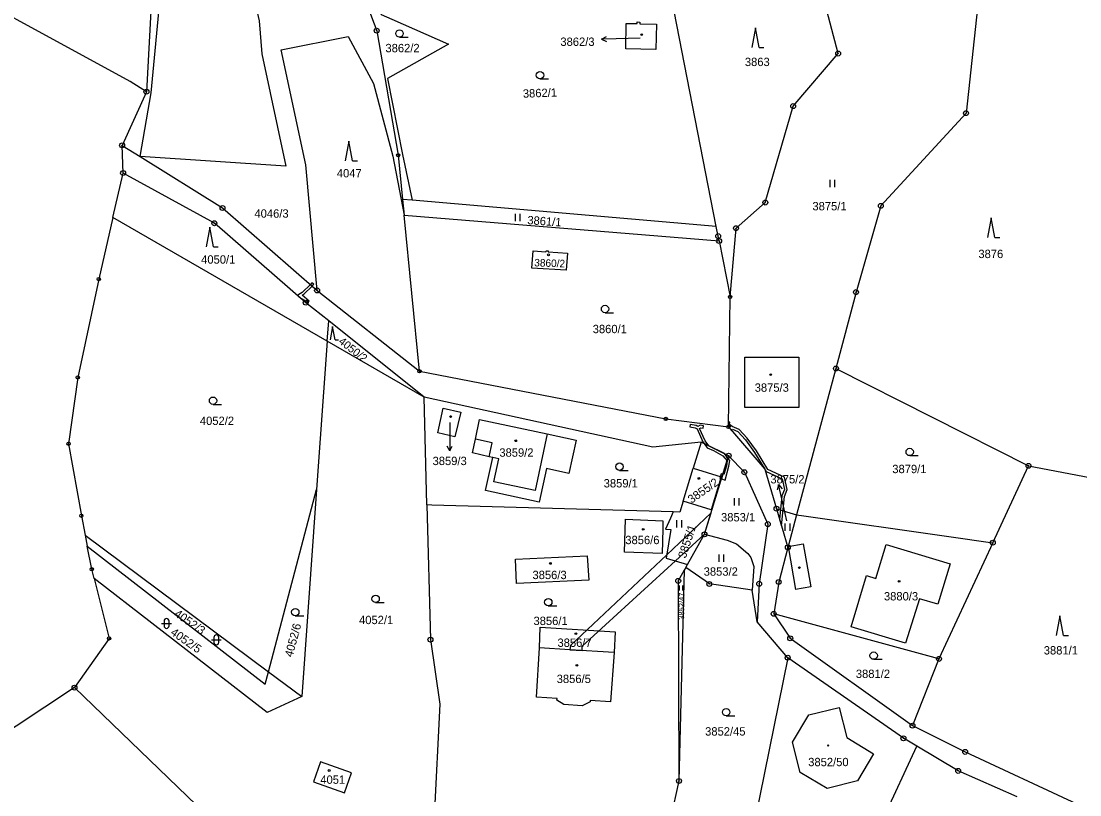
# Model space of a CAD drawing. Extents: x -644096 to -634268, y -1141430 to -1133463.
# Drawn here: x -640343 to -640127.6, y -1137528.7 to -1137371.3 of the extents above; entities that cross this region are included whole.
import ezdxf

# ---------------------------------------------------------------- set-up
doc = ezdxf.new("R2010")
doc.units = 0
for name, color, linetype in [('_CIVIL_CONSTRUCTION', 7, 'Continuous'), ('B_Hranice _3D', 7, 'Continuous'), ('M_Svah_Nasyp', 7, 'Continuous'), ('M_Svah_Zarez', 7, 'Continuous'), ('svrsek_osa_sjezdy', 7, 'Continuous'), ('svrsek_osa_VRT', 7, 'Continuous'), ('svrsek_popisy_VRT', 7, 'Continuous'), ('terminal_VRT', 7, 'Continuous')]:
    doc.layers.add(name, color=color, linetype=linetype)

msp = doc.modelspace()

# ---------------------------------------------------------------- linework, layer by layer
at = {"layer": '_CIVIL_CONSTRUCTION'}
for centre, radius in [((-640270.63, -1137373.26), 0.5), ((-640270.63, -1137373.26), 0.0303), ((-640176.73, -1137377.92), 0.5), ((-640176.73, -1137377.92), 0.0303), ((-640317.48, -1137385.68), 0.5), ((-640317.48, -1137385.68), 0.0303), ((-640185.88, -1137388.6), 0.5), ((-640185.88, -1137388.6), 0.0303), ((-640150.71, -1137390.05), 0.5), ((-640150.71, -1137390.05), 0.0303), ((-640322.44, -1137396.59), 0.5), ((-640322.44, -1137396.59), 0.0303), ((-640266.26, -1137398.59), 0.335), ((-640266.26, -1137398.59), 0.0203), ((-640322.23, -1137402.23), 0.5), ((-640322.23, -1137402.23), 0.0303), ((-640302, -1137409.33), 0.5), ((-640302, -1137409.33), 0.0303), ((-640191.55, -1137408.23), 0.5), ((-640191.55, -1137408.23), 0.0303), ((-640168.05, -1137408.9), 0.5), ((-640168.05, -1137408.9), 0.0303), ((-640303.66, -1137412.44), 0.5), ((-640303.66, -1137412.44), 0.0303), ((-640197.51, -1137413.46), 0.5), ((-640197.51, -1137413.46), 0.0303), ((-640201.15, -1137415.06), 0.5), ((-640200.95, -1137416.05), 0.5), ((-640201.15, -1137415.06), 0.0303), ((-640200.95, -1137416.05), 0.0303), ((-640327.18, -1137423.81), 0.335), ((-640327.18, -1137423.81), 0.0203), ((-640282.76, -1137426.11), 0.5), ((-640282.76, -1137426.11), 0.0303), ((-640173.09, -1137426.45), 0.5), ((-640173.09, -1137426.45), 0.0303), ((-640285.07, -1137428.61), 0.5), ((-640285.07, -1137428.61), 0.0303), ((-640198.71, -1137427.44), 0.335), ((-640198.71, -1137427.44), 0.0203), ((-640177.18, -1137442), 0.5), ((-640331.45, -1137443.82), 0.335), ((-640331.45, -1137443.82), 0.0203), ((-640261.93, -1137442.55), 0.335), ((-640261.93, -1137442.55), 0.0203), ((-640177.18, -1137442), 0.0303), ((-640211.81, -1137452.26), 0.335), ((-640211.81, -1137452.26), 0.0203), ((-640199.05, -1137453.89), 0.335), ((-640199.05, -1137453.89), 0.0203), ((-640333.34, -1137457.32), 0.335), ((-640333.34, -1137457.32), 0.0203), ((-640199.01, -1137459.74), 0.5), ((-640199.01, -1137459.74), 0.0303), ((-640195.81, -1137463.11), 0.5), ((-640195.81, -1137463.11), 0.0303), ((-640137.99, -1137461.8), 0.5), ((-640137.99, -1137461.8), 0.0303), ((-640330.73, -1137471.97), 0.335), ((-640330.73, -1137471.97), 0.0203), ((-640189.27, -1137470.53), 0.5), ((-640189.27, -1137470.53), 0.0303), ((-640191.03, -1137473.66), 0.5), ((-640191.03, -1137473.66), 0.0303), ((-640203.93, -1137475.74), 0.5), ((-640203.93, -1137475.74), 0.0303), ((-640186.97, -1137478.39), 0.5), ((-640186.97, -1137478.39), 0.0303), ((-640145.25, -1137477.45), 0.5), ((-640145.25, -1137477.45), 0.0303), ((-640328.6, -1137482.85), 0.335), ((-640328.6, -1137482.85), 0.0203), ((-640209.27, -1137485.22), 0.5), ((-640209.27, -1137485.22), 0.0303), ((-640202.94, -1137485.84), 0.5), ((-640202.94, -1137485.84), 0.0303), ((-640192.8, -1137485.8), 0.5), ((-640192.8, -1137485.8), 0.0303), ((-640188.83, -1137485.44), 0.5), ((-640188.83, -1137485.44), 0.0303), ((-640189.84, -1137491.91), 0.5), ((-640189.84, -1137491.91), 0.0303), ((-640325.09, -1137496.93), 0.335), ((-640325.09, -1137496.93), 0.0203), ((-640259.69, -1137497.17), 0.5), ((-640259.69, -1137497.17), 0.0303), ((-640186.48, -1137496.9), 0.5), ((-640186.48, -1137496.9), 0.0303), ((-640186.99, -1137500.85), 0.5), ((-640186.99, -1137500.85), 0.0303), ((-640156.21, -1137501.09), 0.5), ((-640156.21, -1137501.09), 0.0303), ((-640332.13, -1137506.94), 0.5), ((-640332.13, -1137506.94), 0.0303), ((-640161.6, -1137514.66), 0.5), ((-640161.6, -1137514.66), 0.0303), ((-640163.44, -1137517.24), 0.5), ((-640163.44, -1137517.24), 0.0303), ((-640150.88, -1137520.01), 0.5), ((-640150.88, -1137520.01), 0.0303), ((-640152.31, -1137523.88), 0.5), ((-640209.12, -1137525.92), 0.5), ((-640152.31, -1137523.88), 0.0303), ((-640209.12, -1137525.92), 0.0303)]:
    msp.add_circle(centre, radius, dxfattribs=at)
at = {"layer": 'B_Hranice _3D'}
for points in [[(-640284.13, -1137424.92), (-640283.75, -1137425.25), (-640283.42, -1137424.86), (-640283.8, -1137424.54)], [(-640284.13, -1137424.92), (-640285.77, -1137426.5), (-640286.46, -1137426.91), (-640286.76, -1137427.14), (-640286.38, -1137427.47), (-640285.33, -1137428.12), (-640284.73, -1137428.66), (-640284.39, -1137428.28), (-640285.78, -1137427.09), (-640285.47, -1137426.9), (-640283.75, -1137425.25)], [(-640206.81, -1137453.39), (-640206.9, -1137453.88), (-640205.79, -1137454.1), (-640205.43, -1137454.27), (-640204.24, -1137456.94), (-640204.02, -1137457.26), (-640203.07, -1137457.73), (-640203.8, -1137456.7), (-640204.92, -1137454.18), (-640204.72, -1137454.07), (-640204.2, -1137454.14), (-640204.13, -1137453.65), (-640204.82, -1137453.55), (-640205.25, -1137453.8), (-640205.63, -1137453.62)], [(-640198.74, -1137452.93), (-640199.04, -1137452.92), (-640199.05, -1137453.89), (-640198.74, -1137454.24), (-640198.37, -1137454.67), (-640198.25, -1137454.36), (-640197.16, -1137454.85), (-640195.59, -1137456.5), (-640193.78, -1137459.06), (-640191.63, -1137462.47), (-640191.41, -1137462.97), (-640188.1, -1137464.46), (-640187.64, -1137466.6), (-640188.16, -1137467.94), (-640188.63, -1137472.73), (-640188.25, -1137474.03), (-640187.66, -1137468.06), (-640187.12, -1137466.64), (-640187.66, -1137464.1), (-640191.07, -1137462.57), (-640193.36, -1137458.78), (-640195.21, -1137456.18), (-640196.86, -1137454.43), (-640198.28, -1137453.79), (-640198.87, -1137453.36)], [(-640204.02, -1137457.26), (-640203.4, -1137458.15), (-640202.06, -1137458.71), (-640200.21, -1137459.75), (-640199.34, -1137460.81), (-640199.16, -1137460.22), (-640199.86, -1137459.32), (-640203.07, -1137457.73)], [(-640199.16, -1137460.22), (-640199.34, -1137460.81), (-640199.47, -1137461.78), (-640199.97, -1137463.58), (-640200.17, -1137463.51), (-640200.46, -1137464.47), (-640199.75, -1137464.69), (-640198.99, -1137461.9), (-640198.76, -1137460.72)], [(-640200.53, -1137463.4), (-640200.83, -1137464.35), (-640200.46, -1137464.47), (-640200.17, -1137463.51)], [(-640202.59, -1137471.38), (-640211.59, -1137479.88), (-640231.18, -1137498.38), (-640231.31, -1137499.24), (-640228.83, -1137499.4), (-640228.79, -1137498.5), (-640209.81, -1137481.12), (-640203.93, -1137475.74)]]:
    msp.add_lwpolyline(points, close=True, dxfattribs=at)
at = {"layer": 'M_Svah_Nasyp'}
for p, q in [((-640247.11, -1137457.11), (-640250.55, -1137456.39)), ((-640235.93, -1137455.29), (-640238.39, -1137466.84)), ((-640247.74, -1137459.95), (-640247.11, -1137457.11)), ((-640245.76, -1137460.35), (-640247.02, -1137460.08)), ((-640246.79, -1137465.05), (-640245.76, -1137460.35)), ((-640238.39, -1137466.84), (-640246.79, -1137465.05)), ((-640186.93, -1137478.24), (-640183.82, -1137477.68)), ((-640186.93, -1137478.24), (-640185.41, -1137486.97)), ((-640183.82, -1137477.68), (-640182.3, -1137486.45)), ((-640169.07, -1137484.72), (-640166.97, -1137477.78)), ((-640166.97, -1137477.78), (-640153.95, -1137481.73)), ((-640153.95, -1137481.73), (-640156.43, -1137489.97)), ((-640174.1, -1137494.53), (-640170.98, -1137484.11)), ((-640170.98, -1137484.11), (-640169.07, -1137484.72)), ((-640182.3, -1137486.45), (-640185.41, -1137486.97)), ((-640160.16, -1137488.84), (-640162.99, -1137497.9)), ((-640156.43, -1137489.97), (-640160.16, -1137488.84)), ((-640162.99, -1137497.9), (-640174.1, -1137494.53))]:
    msp.add_line(p, q, dxfattribs=at)
at = {"layer": 'M_Svah_Zarez'}
for centre, radius in [((-640216.7, -1137374.07), 0.175), ((-640235.67, -1137418.87), 0.175), ((-640190.45, -1137443.25), 0.175), ((-640255.58, -1137451.77), 0.175), ((-640242.33, -1137456.7), 0.175), ((-640205.07, -1137464.37), 0.175), ((-640216.39, -1137474.73), 0.175), ((-640235.28, -1137481.67), 0.175), ((-640184.62, -1137482.52), 0.175), ((-640164.33, -1137485.31), 0.175), ((-640230.1, -1137495.95), 0.175), ((-640229.89, -1137502.4), 0.175), ((-640178.75, -1137518.72), 0.117), ((-640280.3, -1137523.79), 0.175)]:
    msp.add_circle(centre, radius, dxfattribs=at)
at = {"layer": 'svrsek_osa_sjezdy'}
for p, q in [((-640193.57, -1137372.7), (-640194.32, -1137376.7)), ((-640192.82, -1137376.7), (-640193.57, -1137372.7)), ((-640265.98, -1137374.58), (-640264.23, -1137374.58)), ((-640192.82, -1137376.7), (-640191.82, -1137376.7)), ((-640237.4, -1137383.05), (-640235.65, -1137383.05)), ((-640276.28, -1137395.72), (-640277.03, -1137399.72)), ((-640275.53, -1137399.72), (-640276.28, -1137395.72)), ((-640275.53, -1137399.72), (-640274.53, -1137399.72)), ((-640178.38, -1137405.1), (-640178.38, -1137403.6)), ((-640177.38, -1137405.1), (-640177.38, -1137403.6)), ((-640242.41, -1137412.03), (-640242.41, -1137410.53)), ((-640241.41, -1137412.03), (-640241.41, -1137410.53)), ((-640145.6, -1137411.31), (-640146.35, -1137415.31)), ((-640144.85, -1137415.31), (-640145.6, -1137411.31)), ((-640304.61, -1137413.22), (-640305.36, -1137417.22)), ((-640303.86, -1137417.22), (-640304.61, -1137413.22)), ((-640144.85, -1137415.31), (-640143.85, -1137415.31)), ((-640303.86, -1137417.22), (-640302.86, -1137417.22)), ((-640224.16, -1137430.64), (-640222.41, -1137430.64)), ((-640279.59, -1137433.48), (-640280.09, -1137436.16)), ((-640279.09, -1137436.16), (-640279.59, -1137433.48)), ((-640279.09, -1137436.16), (-640278.42, -1137436.16)), ((-640303.93, -1137449.3), (-640302.18, -1137449.3)), ((-640162.17, -1137459.73), (-640160.42, -1137459.73)), ((-640221.23, -1137462.72), (-640219.48, -1137462.72)), ((-640197.84, -1137469.9), (-640197.84, -1137468.4)), ((-640196.84, -1137469.9), (-640196.84, -1137468.4)), ((-640209.53, -1137474.35), (-640209.53, -1137472.85)), ((-640208.53, -1137474.35), (-640208.53, -1137472.85)), ((-640187.52, -1137475.04), (-640187.52, -1137473.54)), ((-640186.52, -1137475.04), (-640186.52, -1137473.54)), ((-640200.96, -1137481.32), (-640200.96, -1137479.82)), ((-640199.96, -1137481.32), (-640199.96, -1137479.82)), ((-640209.01, -1137487.14), (-640209.01, -1137486.14)), ((-640208.34, -1137487.14), (-640208.34, -1137486.14)), ((-640270.85, -1137489.63), (-640269.1, -1137489.63)), ((-640235.71, -1137490.29), (-640233.96, -1137490.29)), ((-640313.89, -1137493.37), (-640313.89, -1137494.37)), ((-640312.89, -1137494.37), (-640312.89, -1137493.37)), ((-640287.19, -1137492.31), (-640285.44, -1137492.31)), ((-640131.6, -1137492.32), (-640132.35, -1137496.32)), ((-640130.85, -1137496.32), (-640131.6, -1137492.32)), ((-640314.39, -1137493.87), (-640312.39, -1137493.87)), ((-640304.25, -1137497.22), (-640302.25, -1137497.22)), ((-640303.75, -1137496.72), (-640303.75, -1137497.72)), ((-640302.75, -1137497.72), (-640302.75, -1137496.72)), ((-640130.85, -1137496.32), (-640129.85, -1137496.32)), ((-640169.5, -1137501.17), (-640167.75, -1137501.17)), ((-640199.5, -1137512.67), (-640197.75, -1137512.67))]:
    msp.add_line(p, q, dxfattribs=at)
for centre in [(-640265.98, -1137373.83), (-640237.4, -1137382.3), (-640224.16, -1137429.89), (-640303.93, -1137448.55), (-640162.17, -1137458.98), (-640221.23, -1137461.97), (-640270.85, -1137488.88), (-640235.71, -1137489.54), (-640287.19, -1137491.56), (-640169.5, -1137500.42), (-640199.5, -1137511.92)]:
    msp.add_circle(centre, 0.75, dxfattribs=at)
for centre, start, end in [((-640313.39, -1137493.37), 0, 180), ((-640313.39, -1137494.37), 180, 359.9879), ((-640303.25, -1137496.72), 0, 180), ((-640303.25, -1137497.72), 180, 359.9879)]:
    msp.add_arc(centre, 0.5, start, end, dxfattribs=at)
at = {"layer": 'svrsek_popisy_VRT'}
for p, q in [((-640224.87, -1137374.97), (-640223.88, -1137374.45)), ((-640221.87, -1137374.92), (-640224.87, -1137374.97)), ((-640224.87, -1137374.97), (-640223.86, -1137375.46)), ((-640216.99, -1137374.81), (-640221.87, -1137374.92)), ((-640255.76, -1137452.98), (-640255.77, -1137455.77)), ((-640255.77, -1137455.77), (-640255.77, -1137458.77)), ((-640255.77, -1137458.77), (-640256.27, -1137457.77)), ((-640255.77, -1137458.77), (-640255.27, -1137457.77)), ((-640188.86, -1137465.59), (-640189.13, -1137466.67)), ((-640188.19, -1137468.51), (-640188.86, -1137465.59)), ((-640188.86, -1137465.59), (-640188.15, -1137466.45)), ((-640187.16, -1137473.02), (-640188.19, -1137468.51))]:
    msp.add_line(p, q, dxfattribs=at)
at = {"layer": 'terminal_VRT'}
for p, q in [((-640201.53, -1137413.13), (-640213.52, -1137351.66)), ((-640317.48, -1137385.68), (-640322.44, -1137396.59)), ((-640318.78, -1137398.87), (-640316.49, -1137385.92)), ((-640322.44, -1137396.59), (-640318.78, -1137398.87)), ((-640322.23, -1137402.23), (-640322.44, -1137396.59)), ((-640324.3, -1137411.25), (-640322.23, -1137402.23)), ((-640265.38, -1137407.59), (-640265.06, -1137410.8)), ((-640263.43, -1137407.76), (-640265.38, -1137407.59)), ((-640201.53, -1137413.13), (-640263.43, -1137407.76)), ((-640280.69, -1137436.44), (-640324.3, -1137411.25)), ((-640261.93, -1137442.55), (-640265.06, -1137410.8)), ((-640265.06, -1137410.8), (-640200.95, -1137416.05)), ((-640200.95, -1137416.05), (-640198.71, -1137427.44)), ((-640282.76, -1137426.11), (-640261.93, -1137442.55)), ((-640199.05, -1137453.89), (-640198.71, -1137427.44)), ((-640280.69, -1137436.44), (-640280.4, -1137432.3)), ((-640260.98, -1137447.83), (-640280.4, -1137432.3)), ((-640280.69, -1137436.44), (-640282.85, -1137466.64)), ((-640260.98, -1137447.83), (-640280.69, -1137436.44)), ((-640177.18, -1137442), (-640185.18, -1137471.74)), ((-640177.18, -1137442), (-640137.99, -1137461.8)), ((-640260.41, -1137469.76), (-640260.98, -1137447.83)), ((-640204.58, -1137456.98), (-640206.22, -1137462.3)), ((-640199.01, -1137459.74), (-640204.58, -1137456.98)), ((-640203.93, -1137475.74), (-640199.01, -1137459.74)), ((-640208.26, -1137468.96), (-640206.22, -1137462.3)), ((-640145.25, -1137477.45), (-640137.99, -1137461.8)), ((-640137.99, -1137461.8), (-640113.16, -1137466.53)), ((-640292.64, -1137503.7), (-640282.85, -1137466.64)), ((-640282.85, -1137466.64), (-640285.87, -1137508.74)), ((-640189.27, -1137470.53), (-640186.97, -1137478.39)), ((-640189.27, -1137470.53), (-640185.18, -1137471.74)), ((-640329.97, -1137475.9), (-640292.64, -1137503.7)), ((-640329.97, -1137475.9), (-640329.52, -1137478.16)), ((-640207.37, -1137481.85), (-640203.93, -1137475.74)), ((-640145.25, -1137477.45), (-640156.21, -1137501.09)), ((-640207.72, -1137482.46), (-640208.03, -1137483.01)), ((-640207.72, -1137482.46), (-640207.37, -1137481.85)), ((-640208.03, -1137483.01), (-640209.12, -1137525.92)), ((-640193.2, -1137493.57), (-640194.24, -1137487.13)), ((-640156.21, -1137501.09), (-640189.84, -1137491.91)), ((-640186.99, -1137500.85), (-640193.2, -1137493.57)), ((-640186.99, -1137500.85), (-640196.16, -1137545.99)), ((-640156.21, -1137501.09), (-640161.6, -1137514.66)), ((-640292.64, -1137503.7), (-640285.87, -1137508.74)), ((-640177.36, -1137554.9), (-640160.74, -1137518.82)), ((-640209.12, -1137525.92), (-640211.96, -1137538.5))]:
    msp.add_line(p, q, dxfattribs=at)
for points in [[(-640327.95, -1137204.66), (-640328.04, -1137213.02), (-640321.85, -1137231.65), (-640317.71, -1137256.53), (-640311.32, -1137307.43), (-640307.58, -1137323.59), (-640297.83, -1137356.91), (-640294.54, -1137371.27), (-640293.98, -1137377.99), (-640289.12, -1137400.84), (-640318.78, -1137398.87)], [(-640341.55, -1137208.21), (-640340.22, -1137247.74), (-640333.9, -1137297.85), (-640335.48, -1137317.25), (-640326.02, -1137336.73), (-640316.4, -1137365.43), (-640317.48, -1137385.68)], [(-640317.48, -1137385.68), (-640320.79, -1137383.58), (-640414.33, -1137332.53)], [(-640279.02, -1137351.14), (-640270.63, -1137373.26), (-640266.26, -1137398.59), (-640265.38, -1137407.59)], [(-640213.52, -1137351.66), (-640253.98, -1137351.74), (-640275.02, -1137356.06), (-640269.73, -1137369.99), (-640267.58, -1137370.9), (-640255.99, -1137376), (-640268.44, -1137383), (-640265.38, -1137398.44), (-640263.43, -1137407.76)], [(-640316.49, -1137385.92), (-640314.58, -1137365.18), (-640316.67, -1137354.45)], [(-640198.71, -1137427.44), (-640197.51, -1137413.46), (-640191.55, -1137408.23), (-640185.88, -1137388.6), (-640176.73, -1137377.92), (-640182.26, -1137356.75)], [(-640147.43, -1137359.74), (-640150.71, -1137390.05), (-640168.05, -1137408.9), (-640173.09, -1137426.45), (-640177.18, -1137442)], [(-640219.96, -1137376.95), (-640219.88, -1137371.8), (-640217.64, -1137371.82), (-640217.62, -1137371.48), (-640217.07, -1137371.5), (-640217.05, -1137371.85), (-640213.72, -1137371.96), (-640213.82, -1137377.1), (-640219.96, -1137376.95)], [(-640282.76, -1137426.11), (-640285.04, -1137400.56), (-640290.07, -1137377.15), (-640276.41, -1137374.42), (-640271.31, -1137384), (-640267.34, -1137398.78), (-640265.06, -1137410.8)], [(-640318.78, -1137398.87), (-640302, -1137409.33), (-640282.76, -1137426.11)], [(-640280.4, -1137432.3), (-640285.07, -1137428.61), (-640303.66, -1137412.44), (-640322.23, -1137402.23)], [(-640324.3, -1137411.25), (-640327.18, -1137423.81), (-640331.45, -1137443.82), (-640333.34, -1137457.32), (-640330.73, -1137471.97), (-640329.97, -1137475.9)], [(-640200.95, -1137416.05), (-640201.15, -1137415.06), (-640201.53, -1137413.13)], [(-640236.18, -1137418.25), (-640236.17, -1137418.05), (-640235.72, -1137418.08), (-640235.73, -1137418.28), (-640231.79, -1137418.53), (-640232.04, -1137422.01), (-640239.06, -1137421.56), (-640238.78, -1137418.08), (-640236.18, -1137418.25)], [(-640195.72, -1137439.7), (-640184.71, -1137439.7), (-640184.72, -1137449.95), (-640195.72, -1137449.94), (-640195.72, -1137439.7)], [(-640261.93, -1137442.55), (-640211.81, -1137452.26), (-640199.05, -1137453.89)], [(-640204.58, -1137456.98), (-640214.47, -1137457.98), (-640260.98, -1137447.83)], [(-640254.71, -1137455.88), (-640258.18, -1137455.08), (-640257.09, -1137450.07), (-640253.53, -1137450.86), (-640254.71, -1137455.88)], [(-640231.53, -1137463.36), (-640236.09, -1137462.36), (-640237.56, -1137469.17), (-640248.49, -1137466.83), (-640247.02, -1137460.08), (-640247.74, -1137459.95), (-640251.11, -1137459.18), (-640250.55, -1137456.39), (-640249.69, -1137452.37), (-640235.93, -1137455.29), (-640230.04, -1137456.56), (-640231.53, -1137463.36)], [(-640199.05, -1137453.89), (-640191.63, -1137462.47), (-640189.27, -1137470.53)], [(-640199.01, -1137459.74), (-640195.81, -1137463.11), (-640191.03, -1137473.66), (-640192.8, -1137485.8), (-640193.2, -1137493.57)], [(-640206.22, -1137462.3), (-640200.5, -1137464.04), (-640202.56, -1137470.73), (-640208.26, -1137468.96)], [(-640260.41, -1137469.76), (-640259.69, -1137497.17), (-640257.81, -1137510.32), (-640258.96, -1137533.2)], [(-640210.33, -1137471.18), (-640259.41, -1137469.79), (-640260.41, -1137469.76)], [(-640208.26, -1137468.96), (-640208.96, -1137471.22), (-640210.33, -1137471.18)], [(-640210.33, -1137471.18), (-640210.84, -1137472.44), (-640211.84, -1137474.69), (-640210.75, -1137474.78), (-640211.7, -1137480.56), (-640207.37, -1137481.85)], [(-640185.18, -1137471.74), (-640186.93, -1137478.24), (-640186.97, -1137478.39)], [(-640185.18, -1137471.74), (-640183.73, -1137471.95), (-640154.18, -1137476.17), (-640145.25, -1137477.45)], [(-640220.21, -1137479.34), (-640220.01, -1137472.67), (-640212.38, -1137472.97), (-640212.43, -1137474.64), (-640212.57, -1137479.61), (-640220.21, -1137479.34)], [(-640203.93, -1137475.74), (-640199.28, -1137476.91), (-640197.41, -1137477.67), (-640195.13, -1137479.67), (-640194.51, -1137480.44), (-640193.89, -1137482.31), (-640194.24, -1137487.13)], [(-640329.52, -1137478.16), (-640293.32, -1137506.26), (-640292.64, -1137503.7)], [(-640328.14, -1137484.7), (-640328.6, -1137482.85), (-640329.52, -1137478.16)], [(-640186.97, -1137478.39), (-640188.83, -1137485.44), (-640189.84, -1137491.91)], [(-640227.79, -1137480.11), (-640227.46, -1137485.08), (-640242.16, -1137485.75), (-640242.39, -1137480.8), (-640227.79, -1137480.11)], [(-640194.24, -1137487.13), (-640202.94, -1137485.84), (-640207.72, -1137482.46)], [(-640328.14, -1137484.7), (-640325.09, -1137496.93), (-640332.13, -1137506.94)], [(-640285.87, -1137508.74), (-640292.93, -1137512.02), (-640328.14, -1137484.7)], [(-640208.03, -1137483.01), (-640209.27, -1137485.22), (-640209.12, -1137525.92)], [(-640189.84, -1137491.91), (-640186.48, -1137496.9), (-640161.6, -1137514.66)], [(-640237.51, -1137498.85), (-640237.36, -1137494.66), (-640222.09, -1137495.61), (-640222.34, -1137499.81)], [(-640222.34, -1137499.81), (-640223.05, -1137509.83), (-640227.21, -1137509.56), (-640227.21, -1137509.85), (-640228.82, -1137510.63), (-640232.53, -1137510.37), (-640233.94, -1137509.48), (-640233.91, -1137509.12), (-640238.1, -1137508.84), (-640237.51, -1137498.85)], [(-640222.34, -1137499.81), (-640231.31, -1137499.24), (-640237.51, -1137498.85)], [(-640160.74, -1137518.82), (-640163.44, -1137517.24), (-640186.99, -1137500.85)], [(-640332.13, -1137506.94), (-640350.07, -1137518.77), (-640356.67, -1137518.16)], [(-640332.13, -1137506.94), (-640307.29, -1137530.85), (-640296.36, -1137541.01), (-640293.98, -1137542.86), (-640293.07, -1137544.14), (-640283.07, -1137553.27), (-640260.4, -1137560.61)], [(-640178.99, -1137527.45), (-640184.44, -1137524.17), (-640185.99, -1137518), (-640182.7, -1137512.45), (-640176.5, -1137510.95), (-640174.99, -1137517.09), (-640169.51, -1137520.38), (-640172.82, -1137525.92), (-640178.99, -1137527.45)], [(-640161.6, -1137514.66), (-640150.88, -1137520.01), (-640128.16, -1137530.58), (-640123.72, -1137538.17)], [(-640140.33, -1137529.17), (-640152.31, -1137523.88), (-640160.74, -1137518.82)], [(-640277.21, -1137528.32), (-640275.77, -1137524.26), (-640282.08, -1137522.02), (-640283.52, -1137526.08), (-640277.21, -1137528.32)]]:
    msp.add_lwpolyline(points, dxfattribs=at)

# ---------------------------------------------------------------- texts
at = {"layer": 'svrsek_osa_VRT'}
for s, p in [('3862/3', (-640233.25, -1137376.36)), ('3862/2', (-640268.85, -1137377.65)), ('3863', (-640195.71, -1137380.46)), ('4047', (-640278.74, -1137403.11)), ('3875/1', (-640181.96, -1137409.82)), ('4046/3', (-640295.5, -1137411.31)), ('3876', (-640148.19, -1137419.53)), ('4050/1', (-640306.35, -1137420.66)), ('3860/1', (-640226.67, -1137434.81)), ('3875/3', (-640193.71, -1137446.73)), ('4052/2', (-640306.61, -1137453.49)), ('3859/2', (-640245.67, -1137459.95)), ('3859/3', (-640259.26, -1137461.65)), ('3879/1', (-640165.71, -1137463.29)), ('3859/1', (-640224.44, -1137466.2)), ('3875/2', (-640190.52, -1137465.38)), ('3853/1', (-640200.56, -1137473.11)), ('3856/6', (-640220.04, -1137477.74)), ('3853/2', (-640204.09, -1137484.16)), ('3856/3', (-640238.93, -1137484.85)), ('3880/3', (-640167.41, -1137489.19)), ('4052/1', (-640274.22, -1137494.01)), ('3856/1', (-640238.72, -1137494.2)), ('3856/7', (-640233.84, -1137498.64)), ('3881/1', (-640134.89, -1137500.19)), ('3856/5', (-640234, -1137506)), ('3881/2', (-640173.13, -1137504.97)), ('3852/45', (-640203.8, -1137516.69)), ('3852/50', (-640182.82, -1137522.92)), ('4051', (-640282.1, -1137526.5))]:
    msp.add_text(s, height=1.7, dxfattribs=at).set_placement(p)
for s, height, rotation, p in [('3862/1', 1.7, 2, (-640240.86, -1137386.91)), ('3861/1', 1.7, 356, (-640240.02, -1137412.62)), ('3860/2', 1.53, 358, (-640238.58, -1137421.21)), ('4050/2', 1.615, 322, (-640278.53, -1137436.75)), ('3855/2', 1.7, 35, (-640206.57, -1137469.53)), ('3855/1', 1.7, 72, (-640207.75, -1137480.74)), ('3852/47', 1.14, 89, (-640208.08, -1137493.12)), ('4052/3', 1.7, 325, (-640311.97, -1137492.26)), ('4052/5', 1.7, 325, (-640312.73, -1137496.04)), ('4052/6', 1.7, 75, (-640287.76, -1137500.84))]:
    msp.add_text(s, height=height, rotation=rotation, dxfattribs=at).set_placement(p)

doc.saveas('drawing.dxf')
